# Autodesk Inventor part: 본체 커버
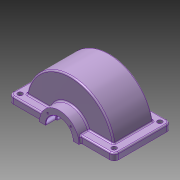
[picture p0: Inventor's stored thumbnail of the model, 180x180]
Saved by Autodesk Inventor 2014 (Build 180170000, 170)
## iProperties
Created: 2023-06
Part Number: 본체 커버
Material: 알루미늄 6061
Document SubType Name: Modeling
Designer: mdu-01
Density: 1 g/cm^3
Appearance: 알루미늄 - 평지(1)
Author: mdu-01
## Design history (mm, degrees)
sketch "스케치1"
  geometry: L1 (0, 70)-(0, -70); L2 (0, 70)-(45, 70); L3 (45, 70)-(45, 45); L4 (45, 45)-(100, 45); L5 (0, 0)-(100, 0); L6 (0, -70)-(45, -70); L7 (45, -70)-(45, -45); L8 (45, -45)-(100, -45); L9 (100, 45)-(100, -45); 1 further point
  constraints: 18 end point, 3 perpendicular, 3 symmetric about line, 2 midpoint, 2 parallel, 1 coincident, 1 vertical
  dimensions: "d0" = 140 distance of L1.start L1.end; "d1" = 90 diameter of L3 L1; "d2" = 90 distance between parallel lines of L8 L4; "d3" = 200 diameter of L9 L1
revolve "회전1" sketch "스케치1" stored, may be unused: angle "d4" = 180 deg
sketch "스케치2"
  geometry: L1 (-10, -110)-(210, -110); L2 (220, -100)-(220, 10); L3 (210, 20)-(-10, 20); L4 (-20, 10)-(-20, -100); L5 (-20, -110)-(220, 20); L6 (220, -110)-(-20, 20); A1 r 10 centre (-10, 10) between (-10, 20) and (-20, 10); A2 r 10 centre (210, 10) between (220, 10) and (210, 20); A3 r 10 centre (210, -100) between (210, -110) and (220, -100); A4 r 10 centre (-10, -100) between (-20, -100) and (-10, -110); 1 further point
  constraints: 12 end point, 8 point on circle, 8 point on line, 8 tangent, 4 centre point, 3 equal radius, 2 midpoint, 2 parallel, 1 horizontal, 1 perpendicular
  dimensions: "d5" = 240 distance of L6.end L5.end; "d6" = 130 distance of L5.end L6.start; "d7" = 10 radius of A1
extrude "돌출1" join sketch "스케치2" distance "d8" = 15; taper "d9" = 0 deg
sketch "스케치3"
  geometry: L1 (0, 70)-(45, 70) reference; L2 (0, -70)-(45, -70) reference; L3 (0, 70)-(0, -70); L4 (31, 70)-(31, 48); L5 (30, 47)-(27.5, 47); L6 (27.5, 47)-(27.5, 32); L7 (27.5, 32)-(87, 32); L8 (0, 0)-(92.097, 0); L9 (31, -70)-(31, -48); L10 (30, -47)-(27.5, -47); L11 (27.5, -47)-(27.5, -32); L12 (27.5, -32)-(87, -32); L13 (87, 32)-(87, -32); L14 (0, 70)-(31, 70); L15 (0, -70)-(31, -70); A1 r 1 centre (30, 48) between (30, 47) and (31, 48); A2 r 1 centre (30, -48) between (31, -48) and (30, -47); 2 further points
  constraints: 26 end point, 5 point on line, 5 symmetric about line, 4 parallel, 4 point on circle, 4 tangent, 3 perpendicular, 2 centre point, 2 collinear, 1 equal radius
  dimensions: "d10" = 1 radius of A1; "d11" = 62 diameter of L4 L3; "d12" = 23 distance between parallel lines of L1 L5; "d13" = 64 distance between parallel lines of L12 L7; "d14" = 55 diameter of L6 L3; "d15" = 87 distance between parallel lines of L13 L3
revolve "회전2" sketch "스케치3" stored, may be unused: angle "d16" = 180 deg
fillet "모깎기1" dims "d17" = 3
fillet "모깎기2" dims "d18" = 3
sketch "스케치4"
  geometry: L1 (-7, -7)-(207, -7); L2 (207, -7)-(207, 97); L3 (207, 97)-(-7, 97); L4 (-7, 97)-(-7, -7); L5 (-7, -7)-(207, 97); L6 (207, -7)-(-7, 97); 1 further point
  constraints: 12 end point, 2 midpoint, 2 parallel, 1 horizontal, 1 perpendicular
  dimensions: "d19" = 214 distance of L3.end L2.end; "d20" = 104 distance of L2.end L1.end
hole "구멍1" sketch "스케치4" at (207, -7), (-7, -7), (207, 97), (-7, 97) diameter "d21" = 6.6; stored, may be unused: countersink angle "d25" = 90 deg, drill point angle "d27" = 118 deg; dims "d22" = 6, "d23" = 11, "d24" = 6.8, "d26" = 8
sketch "스케치5"
  geometry: L1 (-26.163, 26.163)-(26.163, 26.163); L2 (26.163, 26.163)-(26.163, -26.163); L3 (26.163, -26.163)-(-26.163, -26.163); L4 (-26.163, -26.163)-(-26.163, 26.163); A1 r 37 centre (0, 0) between (-26.163, 26.163) and (26.163, -26.163); 1 further point
  constraints: 8 end point, 3 point on circle, 2 parallel, 2 perpendicular, 1 centre point, 1 coincident, 1 horizontal
  dimensions: "d28" = 74 diameter of A1
hole "구멍2" sketch "스케치5" at (-26.163, 26.163), (26.163, 26.163) diameter "d29" = 4.134; stored, may be unused: countersink angle "d33" = 90 deg, drill point angle "d35" = 118 deg; dims "d30" = 10, "d31" = 11, "d32" = 6.8, "d34" = 12
chamfer "모따기1" distance "d36" = 1; stored, may be unused: second distance "d37" = 2, angle "d38" = 45 deg
node "솔리드1"
mirror "대칭1"
